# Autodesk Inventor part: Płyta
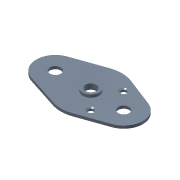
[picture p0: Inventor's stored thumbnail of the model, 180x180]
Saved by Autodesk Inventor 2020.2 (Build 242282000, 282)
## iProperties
Created: 2005-10
Part Number: Płyta
Document SubType Name: Modeling
Designer: F.Stasiak
Density: 1 g/cm^3
Material: Ogólny
Appearance: Stalowoniebieska
Manager: www.cadconsulting.pl
Company: Fabian Stasiak CAD Consulting
Author: F.Stasiak
Subject: Zbiór ćwiczeń. Autodesk Inventor 2020. Kurs podstawowy
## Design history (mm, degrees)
sketch "Szkic1"
  geometry: L1 (72.639, 32.638)-(20.463, 52.843); L2 (18.333, -51.854)-(71.667, -32.998); L3 (0, 0)-(60, 0); L4 (0, 0)-(-65, 0); L5 (-76.667, 32.998)-(-18.889, 53.426); L6 (-75.769, -33.302)-(-16.923, -52.332); A1 r 35 centre (60, 0) between (71.667, -32.998) and (72.639, 32.638); A2 r 35 centre (-65, 0) between (-76.667, 32.998) and (-75.769, -33.302); A3 r 56.667 centre (0, 0) between (20.463, 52.843) and (-18.889, 53.426); A4 r 55 centre (0, 0) between (-16.923, -52.332) and (18.333, -51.854); 1 further point
  constraints: 12 end point, 8 point on circle, 8 tangent, 4 centre point, 1 coincident, 1 collinear, 1 equal radius, 1 horizontal, 1 parallel, 1 other
  dimensions: "d0" = 60 distance of L3.end L3.start; "d1" = 70 diameter of A1; "d18" = 65 distance of point (0, 0) L4.end; "d19" = 55 radius of A4
extrude "Wyciągnięcie proste1" new body sketch "Szkic1" distance "d6" = 5; taper "d7" = 0 deg
sketch "Szkic2"
  geometry: A1 r 35 centre (60, 0) between (71.667, -32.998) and (72.639, 32.638) reference; 3 further points
  constraints: 1 other
hole "Otwór1" sketch "Szkic2" at (0, 0), (60, 0) diameter "d8" = 20; stored, may be unused: countersink angle "d12" = 90 deg, drill point angle "d14" = 118 deg; dims "d9" = 6, "d10" = 4, "d11" = 2, "d13" = 8
sketch "Szkic3"
  geometry: C1 r 10 at (0, 0) reference; C2 r 15 at (0, 0)
  constraints: 1 centre point
  dimensions: "d15" = 30 diameter of C2
extrude "Wyciągnięcie proste2" join sketch "Szkic3" distance "d16" = 5; taper "d17" = 0 deg
sketch "Szkic4"
  geometry: A1 r 35 centre (-65, 0) between (-76.667, 32.998) and (-75.769, -33.302) reference
hole "Otwór2" sketch "Szkic4" at (-65, 0) diameter "d20" = 20; stored, may be unused: countersink angle "d24" = 90 deg, drill point angle "d26" = 118 deg; dims "d21" = 6, "d22" = 4, "d23" = 2, "d25" = 8
sketch "Szkic5"
  geometry: L1 (30, 30)-(30, -30); C1 r 10 at (60, 0) reference
  constraints: 2 end point, 1 vertical
  dimensions: "d27" = 60 distance of L1.end L1.start; "d28" = 30 horizontal distance of L1.end C1.centre (= 0.5 x d27); "d29" = 30 horizontal distance of C1.centre L1.end
hole "Otwór3" sketch "Szkic5" at (30, 30), (30, -30) diameter "d30" = 10; stored, may be unused: countersink angle "d34" = 120 deg, drill point angle "d36" = 118 deg; dims "d31" = 6, "d32" = 15, "d33" = 2, "d35" = 8
node "Bryła1"
node "Korpusy bryłowe"
node "Korpusy powierzchniowe"
